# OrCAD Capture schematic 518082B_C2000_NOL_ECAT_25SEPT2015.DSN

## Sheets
1 SH01 - TITLE PAGE: title: C2000-ET1100 Adapter Board; rev: B; company: TEXAS INSTRUMENTS; note: 518082; note: Preliminary Information - Subject to change
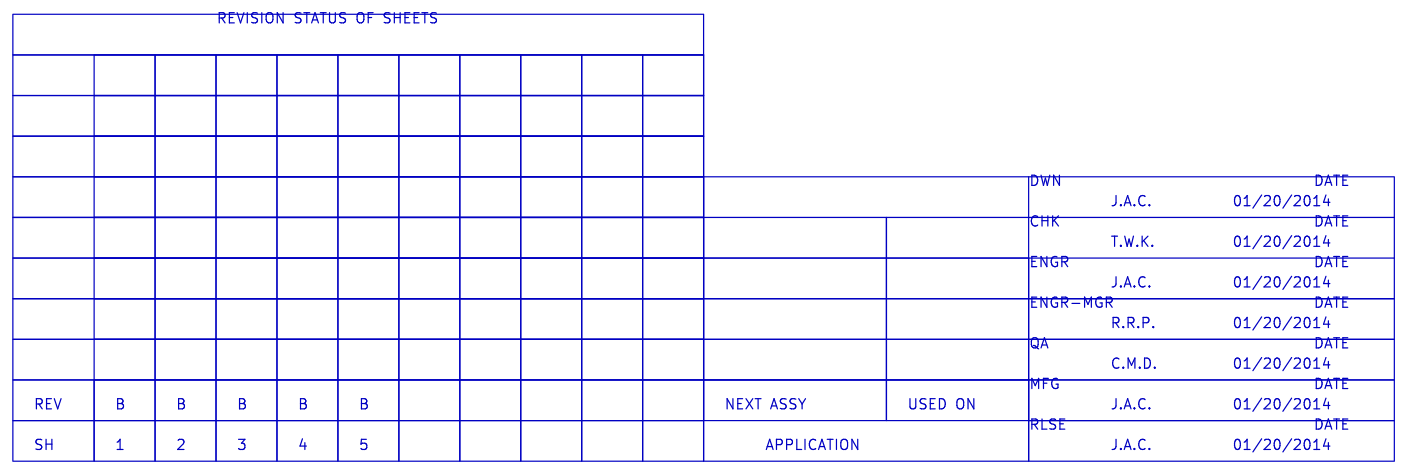
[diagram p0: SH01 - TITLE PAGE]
2 SH03 - ET1100: size C
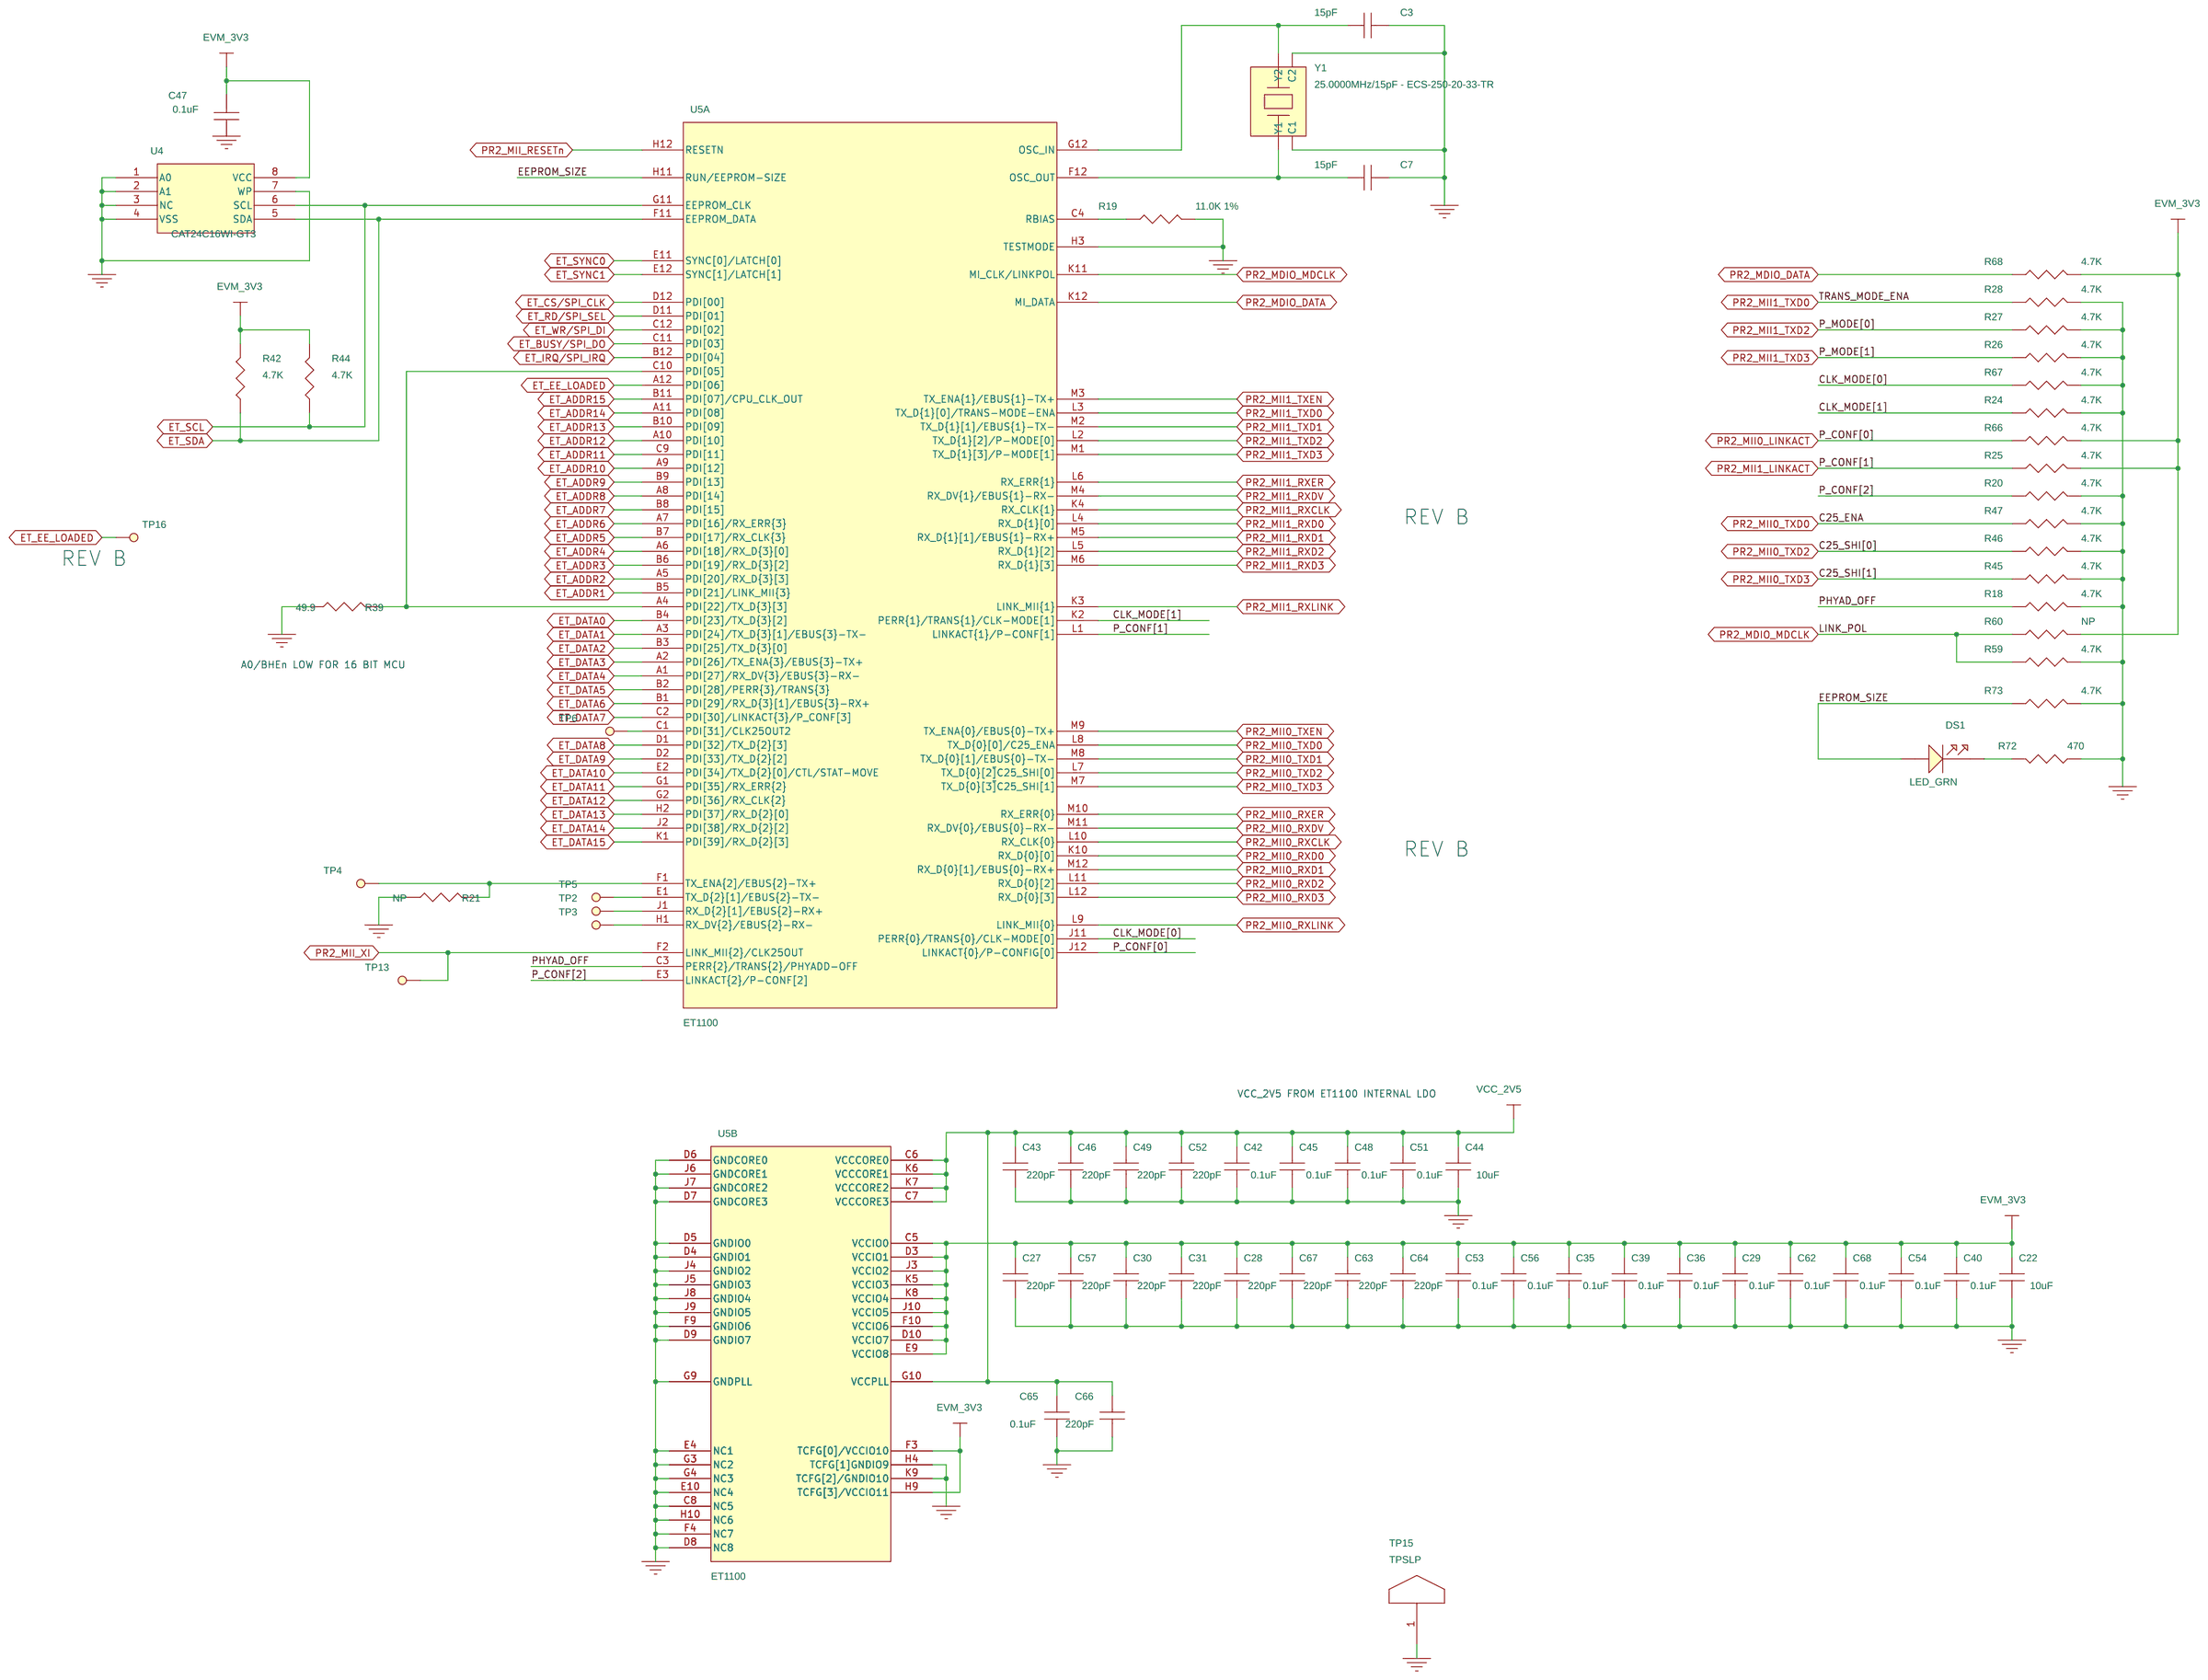
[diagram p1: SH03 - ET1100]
3 SH04 - ICCS2 Ethernet 0: size C
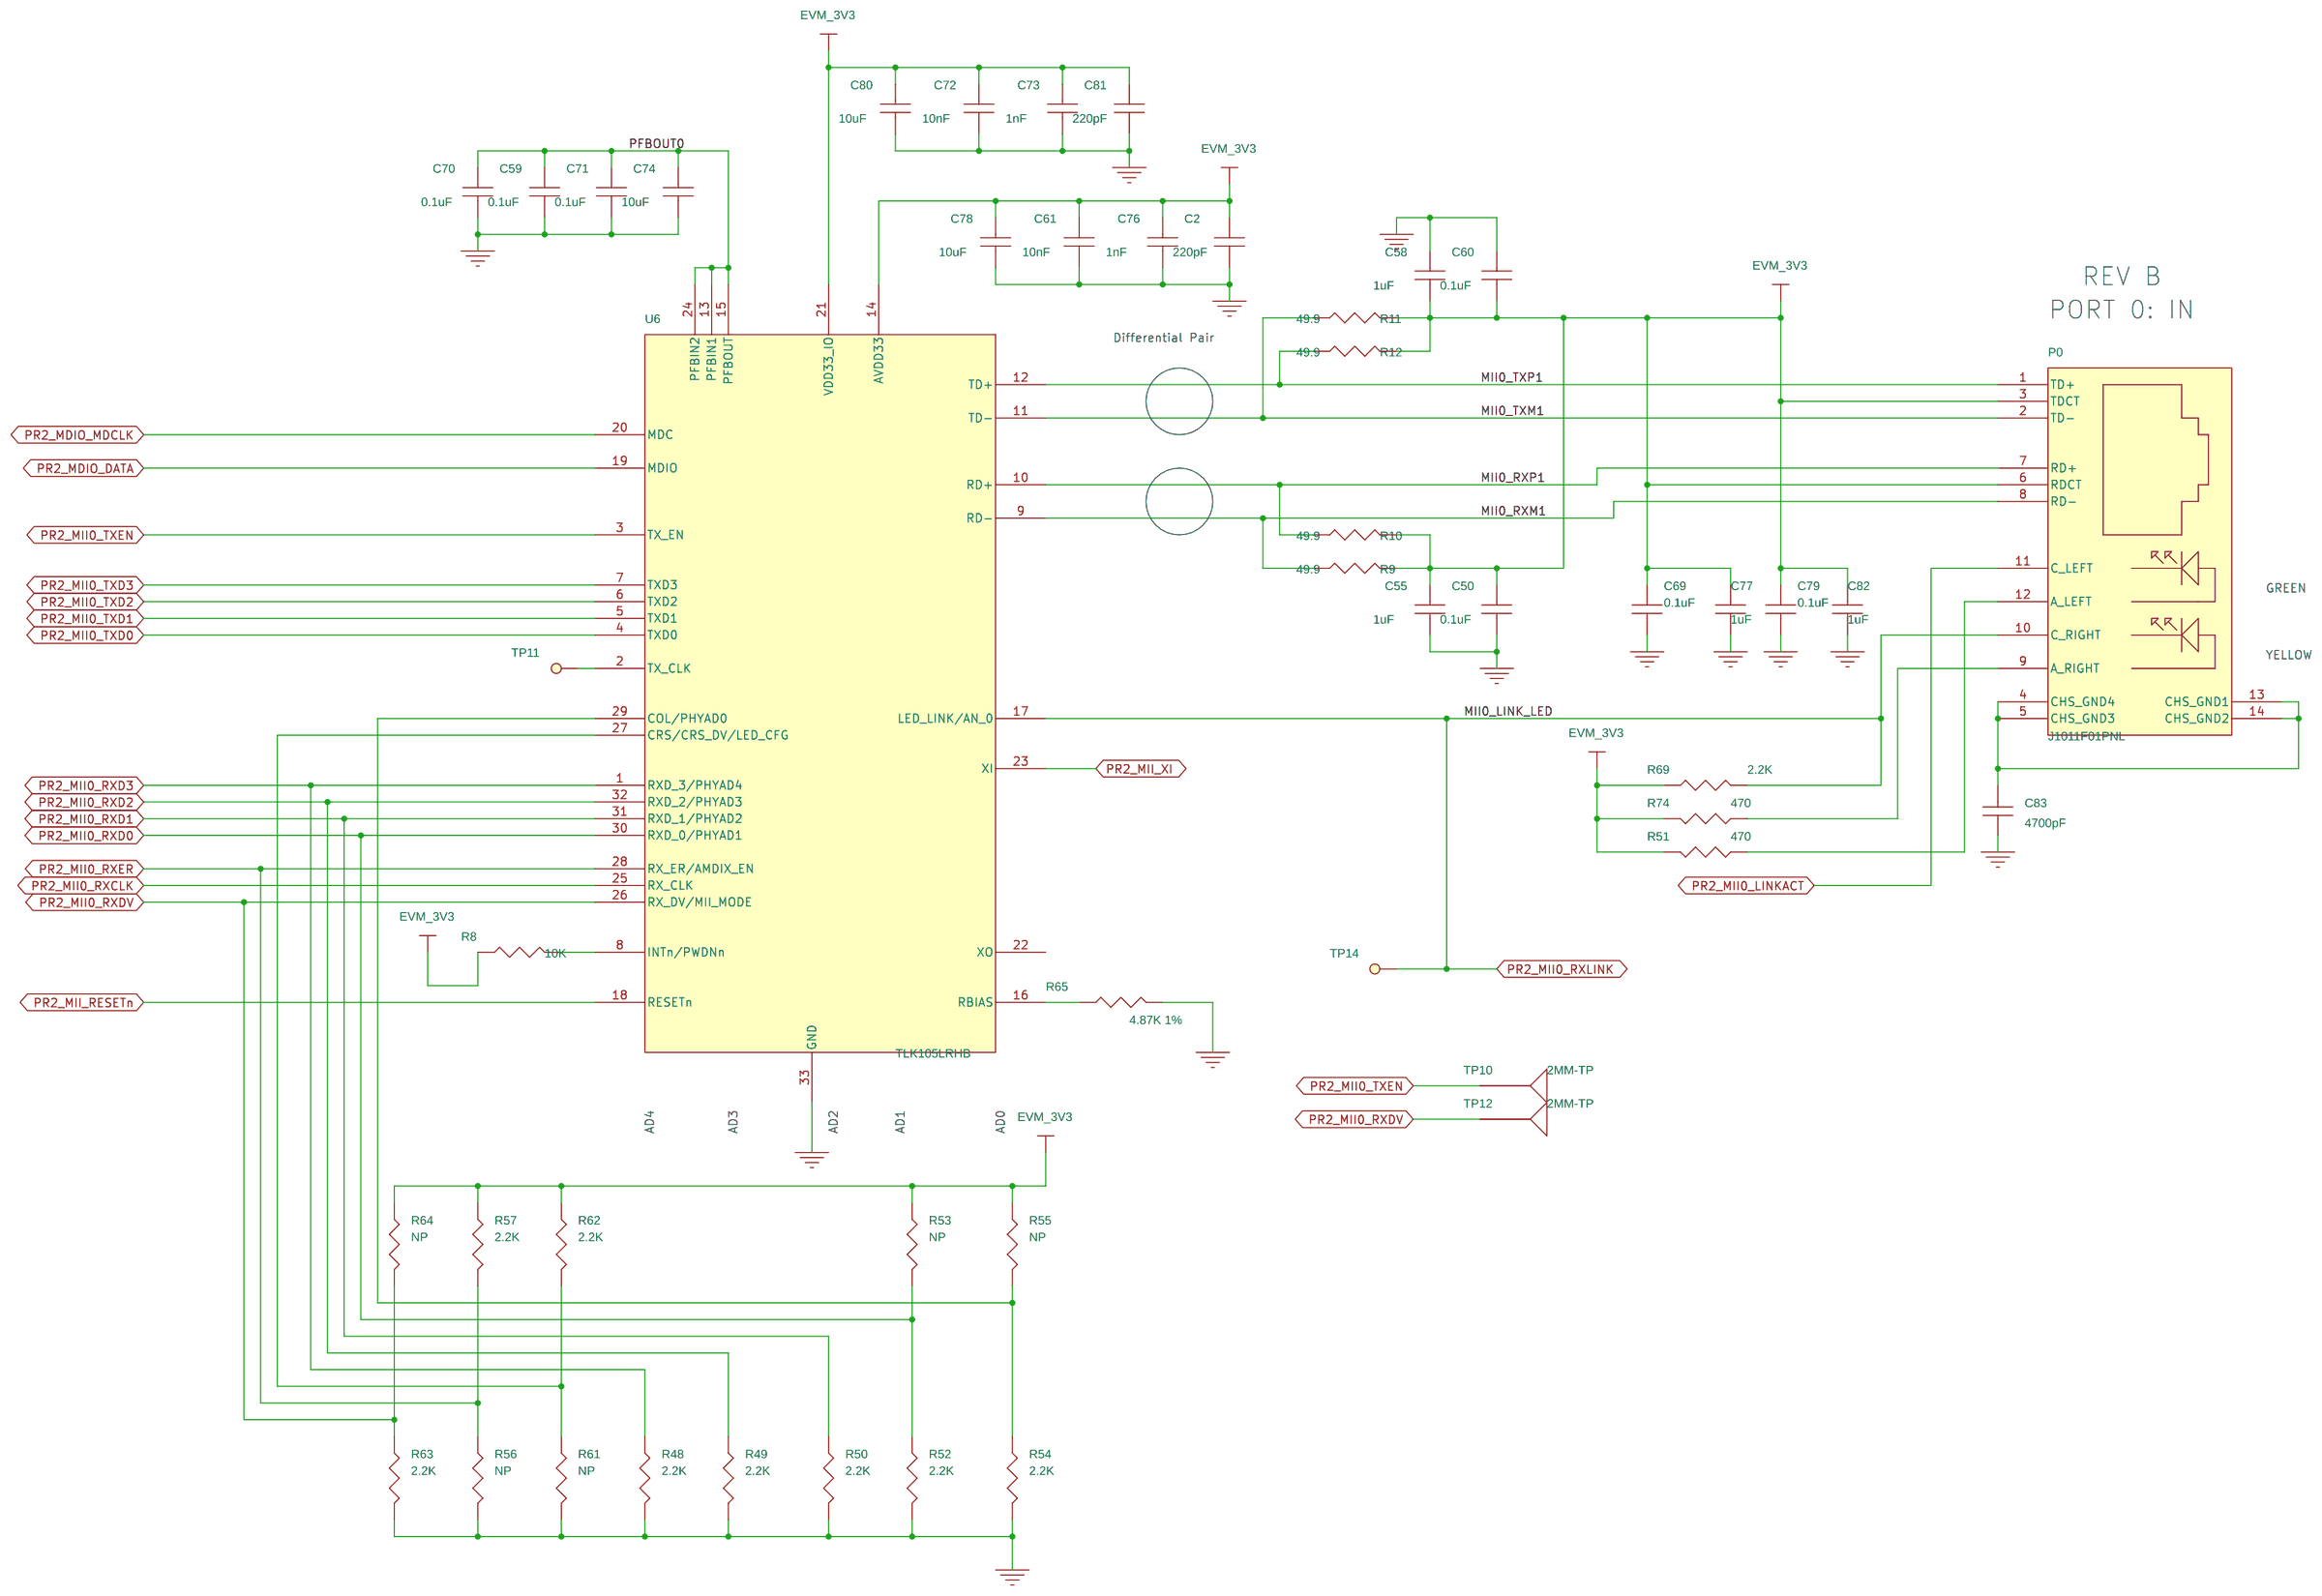
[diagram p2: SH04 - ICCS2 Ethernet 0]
4 SH05 - ICCS1 Ethernet 1: size C
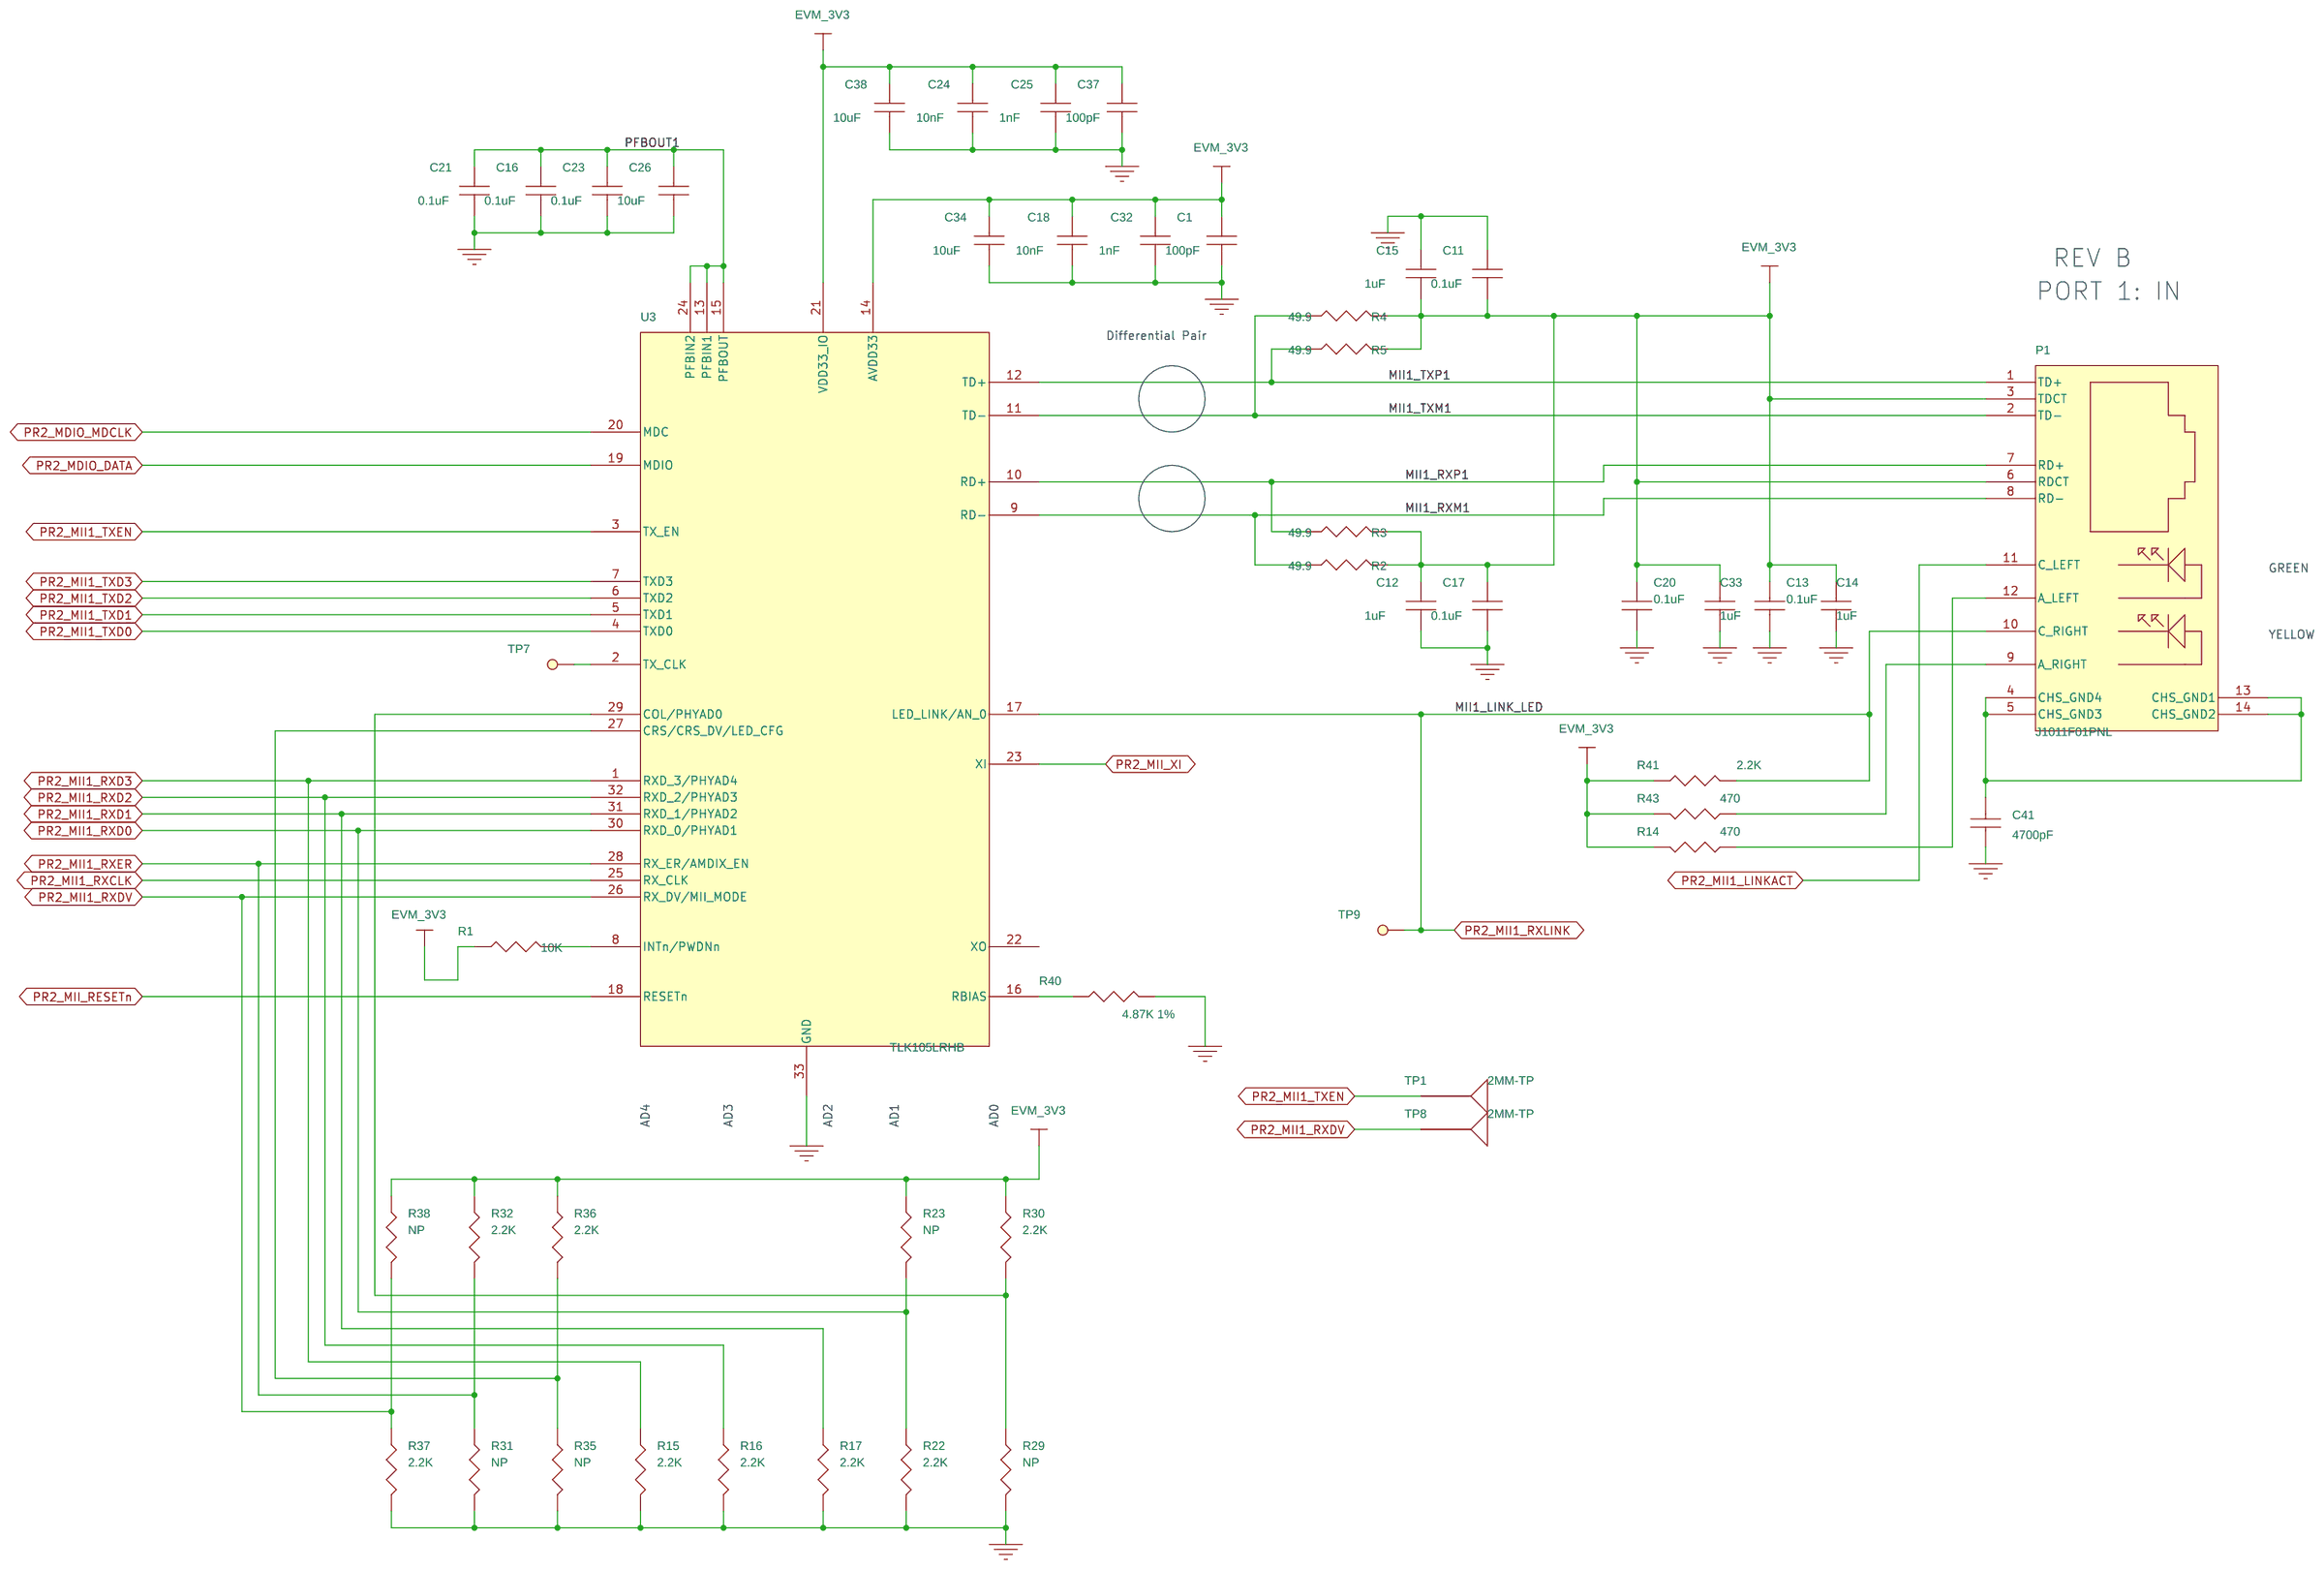
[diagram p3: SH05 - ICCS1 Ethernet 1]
5 SH02 - F28XX INTERFACE/POWER: size C
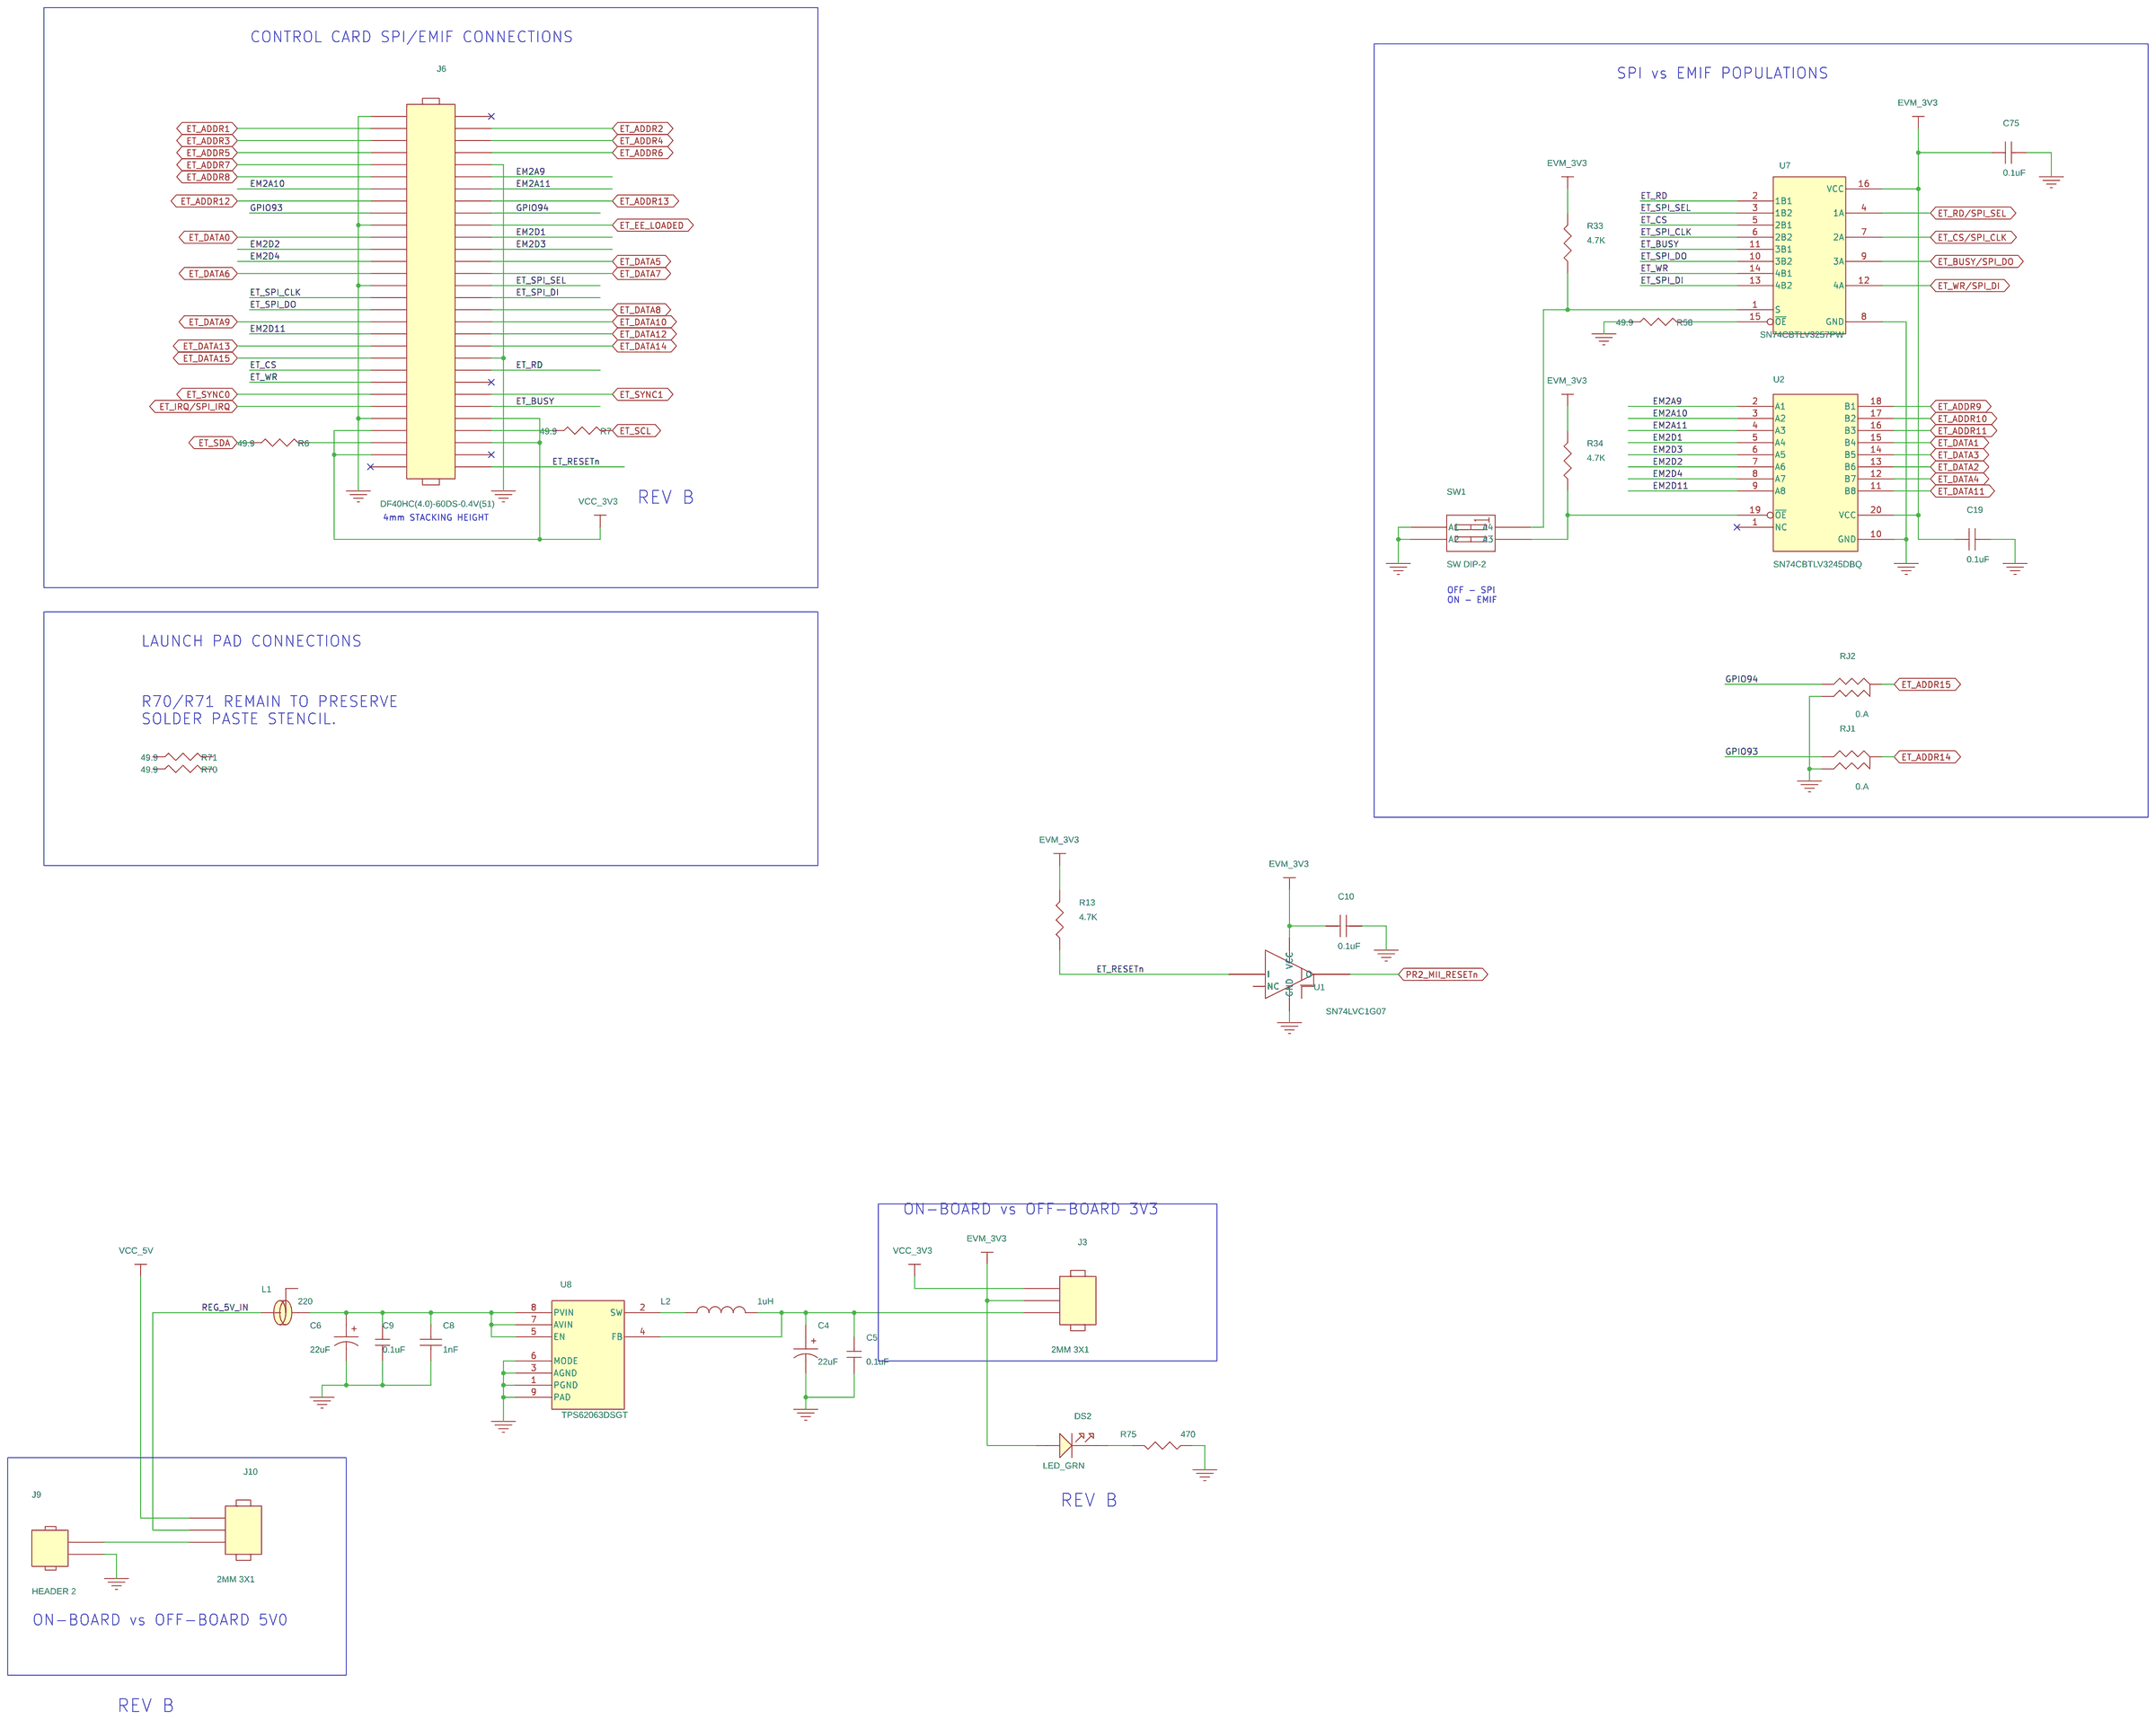
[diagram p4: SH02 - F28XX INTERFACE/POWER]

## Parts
sheet SH02 - F28XX INTERFACE/POWER
C4  22uF  [C1206-40X70]
C5  0.1uF  [c402-25]
C6  22uF  [C1206-40X70]
C8  1nF  [c402-25]
C9  0.1uF  [c402-25]
C10  0.1uF  [c402-25]
C19  0.1uF  [c402-25]
C75  0.1uF  [c402-25]
DS2  LED_GRN  [led1206-59x59]
J3  2MM 3X1  [hdr1x3-6040-2mm]
J6  DF40HC(4.0)-60DS-0.4V(51)  [df40c_60ds]
J9  HEADER 2  [conn2-eh]
J10  2MM 3X1  [hdr1x3-6040-2mm]
L1  220  [l603-35x45]
L2  1uH  [ind-LQH44p]
R6  49.9  [r402-25]
R7  49.9  [r402-25]
R13  4.7K  [r402-25]
R33  4.7K  [r402-25]
R34  4.7K  [r402-25]
R58  49.9  [r402-25]
R70  49.9  [r402-25]
R71  49.9  [r402-25]
R75  470  [r603-35X45]
RJ1  0.A  [JMP402-25]
RJ2  0.A  [JMP402-25]
SW1  SW DIP-2  [sw2-30x50-tda]
U1  SN74LVC1G07  [dck-5]
U2  SN74CBTLV3245DBQ  [dbq20-14X70]
U7  SN74CBTLV3257PW  [tssop16-14x70]
U8  TPS62063DSGT  [dsg8-11x20]
sheet SH03 - ET1100
C3  15pF  [c402-25]
C7  15pF  [c402-25]
C22  10uF  [c603-35x45]
C27  220pF  [c402-25]
C28  220pF  [c402-25]
C29  0.1uF  [c402-25]
C30  220pF  [c402-25]
C31  220pF  [c402-25]
C35  0.1uF  [c402-25]
C36  0.1uF  [c402-25]
C39  0.1uF  [c402-25]
C40  0.1uF  [c402-25]
C42  0.1uF  [c402-25]
C43  220pF  [c402-25]
C44  10uF  [c603-35x45]
C45  0.1uF  [c402-25]
C46  220pF  [c402-25]
C47  0.1uF  [c402-25]
C48  0.1uF  [c402-25]
C49  220pF  [c402-25]
C51  0.1uF  [c402-25]
C52  220pF  [c402-25]
C53  0.1uF  [c402-25]
C54  0.1uF  [c402-25]
C56  0.1uF  [c402-25]
C57  220pF  [c402-25]
C62  0.1uF  [c402-25]
C63  220pF  [c402-25]
C64  220pF  [c402-25]
C65  0.1uF  [c402-25]
C66  220pF  [c402-25]
C67  220pF  [c402-25]
C68  0.1uF  [c402-25]
DS1  LED_GRN  [led1206-59x59]
R18  4.7K  [r402-25]
R19  11.0K 1%  [r402-25]
R20  4.7K  [r402-25]
R21  NP  [r402-25]
R24  4.7K  [r402-25]
R25  4.7K  [r402-25]
R26  4.7K  [r402-25]
R27  4.7K  [r402-25]
R28  4.7K  [r402-25]
R39  49.9  [r402-25]
R42  4.7K  [r402-25]
R44  4.7K  [r402-25]
R45  4.7K  [r402-25]
R46  4.7K  [r402-25]
R47  4.7K  [r402-25]
R59  4.7K  [r402-25]
R60  NP  [r402-25]
R66  4.7K  [r402-25]
R67  4.7K  [r402-25]
R68  4.7K  [r402-25]
R72  470  [r603-35X45]
R73  4.7K  [r402-25]
TP2  RD30  [tp30]
TP3  RD30  [tp30]
TP4  RD30  [tp30]
TP5  RD30  [tp30]
TP6  RD30  [tp30]
TP13  RD30  [tp30]
TP15  TPSLP  [TP1-70X135]
TP16  RD30  [tp30]
U4  CAT24C16WI-GT3  [so8-25x75-295]
U5  ET1100  [bga128-8mm]  (sections A,B)
Y1  25.0000MHz/15pF - ECS-250-20-33-TR  [xtal4-47x51-ecx32]
sheet SH04 - ICCS2 Ethernet 0
C2  220pF  [c402-25]
C50  0.1uF  [c402-25]
C55  1uF  [c603-35x45]
C58  1uF  [c603-35x45]
C59  0.1uF  [c402-25]
C60  0.1uF  [c402-25]
C61  10nF  [c402-25]
C69  0.1uF  [c402-25]
C70  0.1uF  [c402-25]
C71  0.1uF  [c402-25]
C72  10nF  [c402-25]
C73  1nF  [c402-25]
C74  10uF  [c603-35x45]
C76  1nF  [c402-25]
C77  1uF  [c603-35x45]
C78  10uF  [c603-35x45]
C79  0.1uF  [c402-25]
C80  10uF  [c603-35x45]
C81  220pF  [c402-25]
C82  1uF  [c603-35x45]
C83  4700pF  [C1206-40X70]
P0  J1011F01PNL  [RJ45-PULSE_J1-SHLD]
R8  10K  [r402-25]
R9  49.9  [r402-25]
R10  49.9  [r402-25]
R11  49.9  [r402-25]
R12  49.9  [r402-25]
R48  2.2K  [r201-18p5x15]
R49  2.2K  [r201-18p5x15]
R50  2.2K  [r201-18p5x15]
R51  470  [r603-35X45]
R52  2.2K  [r201-18p5x15]
R53  NP  [r201-18p5x15]
R54  2.2K  [r201-18p5x15]
R55  NP  [r201-18p5x15]
R56  NP  [r201-18p5x15]
R57  2.2K  [r201-18p5x15]
R61  NP  [r201-18p5x15]
R62  2.2K  [r201-18p5x15]
R63  2.2K  [r201-18p5x15]
R64  NP  [r201-18p5x15]
R65  4.87K 1%  [r402-25]
R69  2.2K  [r201-18p5x15]
R74  470  [r603-35X45]
TP10  2MM-TP  [TP1-4020]
TP11  RD30  [tp30]
TP12  2MM-TP  [TP1-4020]
TP14  RD30  [tp30]
U6  TLK105LRHB  [QFN32_202SQ]
sheet SH05 - ICCS1 Ethernet 1
C1  100pF  [c402-25]
C11  0.1uF  [c402-25]
C12  1uF  [c603-35x45]
C13  0.1uF  [c402-25]
C14  1uF  [c603-35x45]
C15  1uF  [c603-35x45]
C16  0.1uF  [c402-25]
C17  0.1uF  [c402-25]
C18  10nF  [c402-25]
C20  0.1uF  [c402-25]
C21  0.1uF  [c402-25]
C23  0.1uF  [c402-25]
C24  10nF  [c402-25]
C25  1nF  [c402-25]
C26  10uF  [c603-35x45]
C32  1nF  [c402-25]
C33  1uF  [c603-35x45]
C34  10uF  [c603-35x45]
C37  100pF  [c402-25]
C38  10uF  [c603-35x45]
C41  4700pF  [C1206-40X70]
P1  J1011F01PNL  [RJ45-PULSE_J1-SHLD]
R1  10K  [r402-25]
R2  49.9  [r402-25]
R3  49.9  [r402-25]
R4  49.9  [r402-25]
R5  49.9  [r402-25]
R14  470  [r603-35X45]
R15  2.2K  [r201-18p5x15]
R16  2.2K  [r201-18p5x15]
R17  2.2K  [r201-18p5x15]
R22  2.2K  [r201-18p5x15]
R23  NP  [r201-18p5x15]
R29  NP  [r201-18p5x15]
R30  2.2K  [r201-18p5x15]
R31  NP  [r201-18p5x15]
R32  2.2K  [r201-18p5x15]
R35  NP  [r201-18p5x15]
R36  2.2K  [r201-18p5x15]
R37  2.2K  [r201-18p5x15]
R38  NP  [r201-18p5x15]
R40  4.87K 1%  [r402-25]
R41  2.2K  [r201-18p5x15]
R43  470  [r603-35X45]
TP1  2MM-TP  [TP1-4020]
TP7  RD30  [tp30]
TP8  2MM-TP  [TP1-4020]
TP9  RD30  [tp30]
U3  TLK105LRHB  [QFN32_202SQ]

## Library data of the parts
C4 = CAP_P_0: Part #: 101064-0221R
C5 C9 = CAP_NP_1: Part #: 104446-1100R
C6 = CAP_P_0: .1uf Capacitor, Ceramic, 16V, 10%, 0603; Cost100: 0.0694; Cost10K: 0.038; Mfr: Panasonic; MfrNum: ECJ-1VB1C104K; NCPartnumber: 1C0056; Part #: 101064-0221R; PartName: Cap 100nF Cermc 16V 10% 603; Vendor: Digi-Key; VendorNum: PCC1762CT-ND
C8 C25 C32 C73 C76 = CAP_NP: Part #: 101782-1102R
C10 C11 C16 C17 C19 C21 C23 C29 C35 C36 C39 C40 C42 C45 C48 C50 C51 C53 C54 C56 C59 C60 C62 C65 C68 C70 C71 C75 = CAP_NP: Part #: 104446-1100R
DS1 DS2 = LED_0: Part #: 100823-0001R
J3 J10 = HEADER_3: Part #: 100546-0003R
J6 = HEADER_30x2_SM: Part #: 104687-0060R
J9 = HEADER_2: Part #: 104699-0002R
L1 = FERRITE_CHIP_0: Part #: 101858-2201R
L2 = INDUCTOR_0: Part #: 104075-0100R
R2-R7 R9-R12 R39 R58 R70 R71 = R: Part #: 102145-4990R
R13 R18 R20 R24-R28 R33 R34 R42 R44-R47 R59 R66-R68 R73 = RESISTOR_0: Part #: 102145-4702R
R14 R43 R51 R72 R74 R75 = RESISTOR_0: Part #: 100687-4701R
RJ1 RJ2 = RJUMP3: Part #: 101370-0001R
SW1 = SW_DIP-2: Part #: 101184-0002R
U1 = SN74LVC1GU04_0: Part #: 101057-0007R; Spectrum Part#: 101027-0125
U2 = 74PCT245_0: Part #: 101659-0001R
U7 = SN74CBT3257PW: Part #: 101670-0001R
U8 = TPS62000: Part #: 104063-0001R
C3 C7 = CAP_NP_3: Part #: 101782-1154R
C22 C26 C34 C38 C44 C74 C78 C80 = CAP_NP: Part #: 102963-0101R
C2 C27 C28 C30 C31 C43 C46 C49 C52 C57 C63 C64 C66 C67 C81 = CAP_NP: Part #: 101782-1223R
C47 = CAP_.1_uF_10%_0603: Part #: 104446-1100R
R19 = RESISTOR_0: Part #: 102145-1103R
R21 = R: Part #: R0402-NOPOP
R60 = RESISTOR_0: Part #: R0402-NOPOP
TP2-TP7 TP9 TP11 TP13 TP14 TP16 = TestPoint1: Part #: SMT-TP030
TP15 = SMT-TP: Part #: 104178-0001R
U4 = 24WC256: Part #: 104686-0001R
U5 = ET1100: Part #: 104671-0001R-TI
Y1 = CRYSTAL_4-PIN_0: CRYSTAL, 25MHZ, 25PPM, 3.2X2.5,SMT; Part #: 103274-0025R
C12 C14 C15 C33 C55 C58 C77 C82 = CAP_NP: Part #: 101007-0100R
C18 C24 C61 C72 = CAP_NP: Part #: 101587-1101R
C13 C20 C69 C79 = CAP_NP_0: Part #: 104446-1100R; REV: A
C41 C83 = CAP_NP_0: Part #: 103604-1472R; REV: A
P0 P1 = J1011F01PNL: Part #: 104401-0001R
R1 R8 = R: Part #: 102145-1003R
R15-R17 R22 R30 R32 R36 R37 R41 R48-R50 R52 R54 R57 R62 R63 R69 = RESISTOR_0: Part #: 103158-2202R
R23 R29 R31 R35 R38 R53 R55 R56 R61 R64 = RESISTOR_0: Part #: R0201-NOPOP
R40 R65 = RESISTOR_0: Part #: 102145-4872R
TP1 TP8 TP10 TP12 = TEST_POINT_1: Part #: NO-POP
U3 U6 = TLK105: Part #: 104684-0001R
C1 C37 = CAP_NP: Part #: 101782-1103R

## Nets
GND: C1.2 C2.2 C3.2 C4.2 C5.2 C6.2 C7.2 C8.2 C9.2 C10.2 C11.1 C12.2 C13.2 C14.2 C15.1 C16.2 C17.2 C18.2 C19.2 C20.2 C21.2 C22.2 C23.2 C24.2 C25.2 C26.2 C27.2 C28.2 C29.2 C30.2 C31.2 C32.2 C33.2 C34.2 C35.2 C36.2 C37.2 C38.2 C39.2 C40.2 C41.1 C42.2 C43.2 C44.2 C45.2 C46.2 C47.1 C48.2 C49.2 C50.2 C51.2 C52.2 C53.2 C54.2 C55.2 C56.2 C57.2 C58.1 C59.2 C60.1 C61.2 C62.2 C63.2 C64.2 C65.2 C66.2 C67.2 C68.2 C69.2 C70.2 C71.2 C72.2 C73.2 C74.2 C75.2 C76.2 C77.2 C78.2 C79.2 C80.2 C81.2 C82.2 C83.1 J6.1 J6.10 J6.19 J6.29 J6.42 J6.51 J9.2 R15.2 R16.2 R17.2 R18.2 R19.2 R20.2 R21.1 R22.2 R24.2 R26.2 R27.2 R28.2 R29.2 R31.2 R35.2 R37.2 R39.1 R40.2 R45.2 R46.2 R47.2 R48.2 R49.2 R50.2 R52.2 R54.2 R56.2 R58.1 R59.2 R61.2 R63.2 R65.2 R67.2 R72.1 R73.2 R75.1 RJ1.3 RJ2.3 SW1.1(A1) SW1.2(A2) TP15.1 U1.3(GND) U2.10(GND) U3.33(GND) U4.1(A0) U4.2(A1) U4.3(NC) U4.4(VSS) U4.7(WP) U5.C8(NC5) U5.D4(GNDIO1) U5.D5(GNDIO0) U5.D6(GNDCORE0) U5.D7(GNDCORE3) U5.D8(NC8) U5.D9(GNDIO7) U5.E4(NC1) U5.E10(NC4) U5.F4(NC7) U5.F9(GNDIO6) U5.G3(NC2) U5.G4(NC3) U5.G9(GNDPLL) U5.H3(TESTMODE) U5.H4(TCFG[1]GNDIO9) U5.H10(NC6) U5.J4(GNDIO2) U5.J5(GNDIO3) U5.J6(GNDCORE1) U5.J7(GNDCORE2) U5.J8(GNDIO4) U5.J9(GNDIO5) U5.K9(TCFG[2]/GNDIO10) U6.33(GND) U7.8(GND) U8.1(PGND) U8.3(AGND) U8.6(MODE) U8.9(PAD) Y1.2(C1) Y1.4(C2)
VCC_2V5: C42.1 C43.1 C44.1 C45.1 C46.1 C48.1 C49.1 C51.1 C52.1 C65.1 C66.1 U5.C6(VCCCORE0) U5.C7(VCCCORE3) U5.G10(VCCPLL) U5.K6(VCCCORE1) U5.K7(VCCCORE2)
VCC_3V3: J3.1 J6.52 J6.53 J6.56 J6.57
VCC_5V: J10.1
CLK_MODE[0]: R67.1 U5.J11(PERR{0}/TRANS{0}/CLK-MODE[0])
CLK_MODE[1]: R24.1 U5.K2(PERR{1}/TRANS{1}/CLK-MODE[1])
EEPROM_SIZE: DS1.2(ANODE) R73.1 U5.H11(RUN/EEPROM-SIZE)
EM2A9: J6.12 U2.2(A1)
EM2A10: J6.13 U2.3(A2)
EM2A11: J6.14 U2.4(A3)
EM2D1: J6.22 U2.5(A4)
EM2D2: J6.23 U2.7(A6)
EM2D3: J6.24 U2.6(A5)
EM2D4: J6.25 U2.8(A7)
EM2D11: J6.37 U2.9(A8)
ET_ADDR1: J6.3 U5.B5(PDI[21]/LINK_MII{3})
ET_ADDR2: J6.4 U5.A5(PDI[20]/RX_D{3}[3])
ET_ADDR3: J6.5 U5.B6(PDI[19]/RX_D{3}[2])
ET_ADDR4: J6.6 U5.A6(PDI[18]/RX_D{3}[0])
ET_ADDR5: J6.7 U5.B7(PDI[17]/RX_CLK{3})
ET_ADDR6: J6.8 U5.A7(PDI[16]/RX_ERR{3})
ET_ADDR7: J6.9 U5.B8(PDI[15])
ET_ADDR8: J6.11 U5.A8(PDI[14])
ET_ADDR9: U2.18(B1) U5.B9(PDI[13])
ET_ADDR10: U2.17(B2) U5.A9(PDI[12])
ET_ADDR11: U2.16(B3) U5.C9(PDI[11])
ET_ADDR12: J6.15 U5.A10(PDI[10])
ET_ADDR13: J6.16 U5.B10(PDI[09])
ET_ADDR14: RJ1.2 U5.A11(PDI[08])
ET_ADDR15: RJ2.2 U5.B11(PDI[07]/CPU_CLK_OUT)
ET_BUSY: J6.50 U7.11(3B1)
ET_BUSY/SPI_DO: U5.C11(PDI[03]) U7.9(3A)
ET_CS: J6.43 U7.5(2B1)
ET_CS/SPI_CLK: U5.D12(PDI[00]) U7.7(2A)
ET_DATA0: J6.21 U5.B4(PDI[23]/TX_D{3}[2])
ET_DATA1: U2.15(B4) U5.A3(PDI[24]/TX_D{3}[1]/EBUS{3}-TX-)
ET_DATA2: U2.13(B6) U5.B3(PDI[25]/TX_D{3}[0])
ET_DATA3: U2.14(B5) U5.A2(PDI[26]/TX_ENA{3}/EBUS{3}-TX+)
ET_DATA4: U2.12(B7) U5.A1(PDI[27]/RX_DV{3}/EBUS{3}-RX-)
ET_DATA5: J6.26 U5.B2(PDI[28]/PERR{3}/TRANS{3})
ET_DATA6: J6.27 U5.B1(PDI[29]/RX_D{3}[1]/EBUS{3}-RX+)
ET_DATA7: J6.28 U5.C2(PDI[30]/LINKACT{3}/P_CONF[3])
ET_DATA8: J6.34 U5.D1(PDI[32]/TX_D{2}[3])
ET_DATA9: J6.35 U5.D2(PDI[33]/TX_D{2}[2])
ET_DATA10: J6.36 U5.E2(PDI[34]/TX_D{2}[0]/CTL/STAT-MOVE)
ET_DATA11: U2.11(B8) U5.G1(PDI[35]/RX_ERR{2})
ET_DATA12: J6.38 U5.G2(PDI[36]/RX_CLK{2})
ET_DATA13: J6.39 U5.H2(PDI[37]/RX_D{2}[0])
ET_DATA14: J6.40 U5.J2(PDI[38]/RX_D{2}[2])
ET_DATA15: J6.41 U5.K1(PDI[39]/RX_D{2}[3])
ET_EE_LOADED: J6.20 TP16.1 U5.A12(PDI[06])
ET_IRQ/SPI_IRQ: J6.49 U5.B12(PDI[04])
ET_RD: J6.44 U7.2(1B1)
ET_RD/SPI_SEL: U5.D11(PDI[01]) U7.4(1A)
ET_RESETn: J6.60 R13.1 U1.2(I)
ET_SCL: R7.2 R44.1 U4.6(SCL) U5.G11(EEPROM_CLK)
ET_SDA: R6.1 R42.1 U4.5(SDA) U5.F11(EEPROM_DATA)
ET_SPI_CLK: J6.31 U7.6(2B2)
ET_SPI_DI: J6.32 U7.13(4B2)
ET_SPI_DO: J6.33 U7.10(3B2)
ET_SPI_SEL: J6.30 U7.3(1B2)
ET_SYNC0: J6.47 U5.E11(SYNC[0]/LATCH[0])
ET_SYNC1: J6.48 U5.E12(SYNC[1]/LATCH[1])
ET_WR: J6.45 U7.14(4B1)
ET_WR/SPI_DI: U5.C12(PDI[02]) U7.12(4A)
EVM_3V3: C1.1 C2.1 C10.1 C11.2 C12.1 C13.1 C14.1 C15.2 C17.1 C18.1 C19.1 C20.1 C22.1 C24.1 C25.1 C27.1 C28.1 C29.1 C30.1 C31.1 C32.1 C33.1 C34.1 C35.1 C36.1 C37.1 C38.1 C39.1 C40.1 C47.2 C50.1 C53.1 C54.1 C55.1 C56.1 C57.1 C58.2 C60.2 C61.1 C62.1 C63.1 C64.1 C67.1 C68.1 C69.1 C72.1 C73.1 C75.1 C76.1 C77.1 C78.1 C79.1 C80.1 C81.1 C82.1 DS2.2(ANODE) J3.2 P0.3(TDCT) P0.6(RDCT) P1.3(TDCT) P1.6(RDCT) R1.1 R2.2 R3.2 R4.2 R5.2 R8.1 R9.2 R10.2 R11.2 R12.2 R13.2 R14.2 R23.1 R25.2 R30.1 R32.1 R33.2 R34.2 R36.1 R38.1 R41.1 R42.2 R43.2 R44.2 R51.2 R53.1 R55.1 R57.1 R60.2 R62.1 R64.1 R66.2 R68.2 R69.1 R74.2 U1.5(VCC) U2.20(VCC) U3.14(AVDD33) U3.21(VDD33_IO) U4.8(VCC) U5.C5(VCCIO0) U5.D3(VCCIO1) U5.D10(VCCIO7) U5.E9(VCCIO8) U5.F3(TCFG[0]/VCCIO10) U5.F10(VCCIO6) U5.H9(TCFG[3]/VCCIO11) U5.J3(VCCIO2) U5.J10(VCCIO5) U5.K5(VCCIO3) U5.K8(VCCIO4) U6.14(AVDD33) U6.21(VDD33_IO) U7.16(VCC)
GPIO93: J6.17 RJ1.1
GPIO94: J6.18 RJ2.1
MII0_RXM1: P0.8(RD-) R9.1 U6.9(RD-)
MII0_RXP1: P0.7(RD+) R10.1 U6.10(RD+)
MII0_TXM1: P0.2(TD-) R11.1 U6.11(TD-)
MII0_TXP1: P0.1(TD+) R12.1 U6.12(TD+)
MII1_RXM1: P1.8(RD-) R2.1 U3.9(RD-)
MII1_RXP1: P1.7(RD+) R3.1 U3.10(RD+)
MII1_TXM1: P1.2(TD-) R4.1 U3.11(TD-)
MII1_TXP1: P1.1(TD+) R5.1 U3.12(TD+)
P_CONF[2]: R20.1 U5.E3(LINKACT{2}/P-CONF[2])
PFBOUT0: C59.1 C70.1 C71.1 C74.1 U6.13(PFBIN1) U6.15(PFBOUT) U6.24(PFBIN2)
PFBOUT1: C16.1 C21.1 C23.1 C26.1 U3.13(PFBIN1) U3.15(PFBOUT) U3.24(PFBIN2)
PHYAD_OFF: R18.1 U5.C3(PERR{2}/TRANS{2}/PHYADD-OFF)
PR2_MDIO_DATA: R68.1 U3.19(MDIO) U5.K12(MI_DATA) U6.19(MDIO)
PR2_MDIO_MDCLK: R59.1 R60.1 U3.20(MDC) U5.K11(MI_CLK/LINKPOL) U6.20(MDC)
PR2_MII0_LINKACT: P0.11(C_LEFT) R66.1 U5.J12(LINKACT{0}/P-CONFIG[0])
PR2_MII0_RXCLK: U5.L10(RX_CLK{0}) U6.25(RX_CLK)
PR2_MII0_RXD0: R52.1 R53.2 U5.K10(RX_D{0}[0]) U6.30(RXD_0/PHYAD1)
PR2_MII0_RXD1: R50.1 U5.M12(RX_D{0}[1]/EBUS{0}-RX+) U6.31(RXD_1/PHYAD2)
PR2_MII0_RXD2: R49.1 U5.L11(RX_D{0}[2]) U6.32(RXD_2/PHYAD3)
PR2_MII0_RXD3: R48.1 U5.L12(RX_D{0}[3]) U6.1(RXD_3/PHYAD4)
PR2_MII0_RXDV: R63.1 R64.2 TP12.1 U5.M11(RX_DV{0}/EBUS{0}-RX-) U6.26(RX_DV/MII_MODE)
PR2_MII0_RXER: R56.1 R57.2 U5.M10(RX_ERR{0}) U6.28(RX_ER/AMDIX_EN)
PR2_MII0_RXLINK: P0.10(C_RIGHT) R69.2 TP14.1 U5.L9(LINK_MII{0}) U6.17(LED_LINK/AN_0)
PR2_MII0_TXD0: R47.1 U5.L8(TX_D{0}[0]/C25_ENA) U6.4(TXD0)
PR2_MII0_TXD1: U5.M8(TX_D{0}[1]/EBUS{0}-TX-) U6.5(TXD1)
PR2_MII0_TXD2: R46.1 U5.L7(TX_D{0}[2~{]}C25_SHI[0]) U6.6(TXD2)
PR2_MII0_TXD3: R45.1 U5.M7(TX_D{0}[3~{]}C25_SHI[1]) U6.7(TXD3)
PR2_MII0_TXEN: TP10.1 U5.M9(TX_ENA{0}/EBUS{0}-TX+) U6.3(TX_EN)
PR2_MII1_LINKACT: P1.11(C_LEFT) R25.1 U5.L1(LINKACT{1}/P-CONF[1])
PR2_MII1_RXCLK: U3.25(RX_CLK) U5.K4(RX_CLK{1})
PR2_MII1_RXD0: R22.1 R23.2 U3.30(RXD_0/PHYAD1) U5.L4(RX_D{1}[0])
PR2_MII1_RXD1: R17.1 U3.31(RXD_1/PHYAD2) U5.M5(RX_D{1}[1]/EBUS{1}-RX+)
PR2_MII1_RXD2: R16.1 U3.32(RXD_2/PHYAD3) U5.L5(RX_D{1}[2])
PR2_MII1_RXD3: R15.1 U3.1(RXD_3/PHYAD4) U5.M6(RX_D{1}[3])
PR2_MII1_RXDV: R37.1 R38.2 TP8.1 U3.26(RX_DV/MII_MODE) U5.M4(RX_DV{1}/EBUS{1}-RX-)
PR2_MII1_RXER: R31.1 R32.2 U3.28(RX_ER/AMDIX_EN) U5.L6(RX_ERR{1})
PR2_MII1_RXLINK: P1.10(C_RIGHT) R41.2 TP9.1 U3.17(LED_LINK/AN_0) U5.K3(LINK_MII{1})
PR2_MII1_TXD0: R28.1 U3.4(TXD0) U5.L3(TX_D{1}[0]/TRANS-MODE-ENA)
PR2_MII1_TXD1: U3.5(TXD1) U5.M2(TX_D{1}[1]/EBUS{1}-TX-)
PR2_MII1_TXD2: R27.1 U3.6(TXD2) U5.L2(TX_D{1}[2]/P-MODE[0])
PR2_MII1_TXD3: R26.1 U3.7(TXD3) U5.M1(TX_D{1}[3]/P-MODE[1])
PR2_MII1_TXEN: TP1.1 U3.3(TX_EN) U5.M3(TX_ENA{1}/EBUS{1}-TX+)
PR2_MII_RESETn: U1.4(O) U3.18(RESETn) U5.H12(RESETN) U6.18(RESETn)
PR2_MII_XI: TP13.1 U3.23(XI) U5.F2(LINK_MII{2}/CLK25OUT) U6.23(XI)
REG_5V_IN: J10.2 L1.1
N21750864: R54.1 R55.2 U6.29(COL/PHYAD0)
N21750872: R61.1 R62.2 U6.27(CRS/CRS_DV/LED_CFG)
N21750878: R65.1 U6.16(RBIAS)
N21751363: P0.9(A_RIGHT) R74.1
N21751679: C83.2 P0.4(CHS_GND4) P0.5(CHS_GND3) P0.13(CHS_GND1) P0.14(CHS_GND2)
N21752228: R8.2 U6.8(INTn/PWDNn)
N21760792: R29.1 R30.2 U3.29(COL/PHYAD0)
N21760889: R35.1 R36.2 U3.27(CRS/CRS_DV/LED_CFG)
N21760945: P1.9(A_RIGHT) R43.1
N21760963: C41.2 P1.4(CHS_GND4) P1.5(CHS_GND3) P1.13(CHS_GND1) P1.14(CHS_GND2)
N21761103: R40.1 U3.16(RBIAS)
N21761294: R1.2 U3.8(INTn/PWDNn)
N21764803: C7.1 U5.F12(OSC_OUT) Y1.1(Y1)
N21764807: C3.1 U5.G12(OSC_IN) Y1.3(Y2)
N21767563: R19.1 U5.C4(RBIAS)
N21781367: TP7.1 U3.2(TX_CLK)
N21781382: TP11.1 U6.2(TX_CLK)
N21785424: DS1.1(cathode) R72.2
N21788279: P1.12(A_LEFT) R14.1
N21789027: P0.12(A_LEFT) R51.1
N21791162: R21.2 TP4.1 U5.F1(TX_ENA{2]/EBUS{2}-TX+)
N21791165: TP5.1 U5.E1(TX_D{2}[1]/EBUS{2}-TX-)
N21791168: TP2.1 U5.J1(RX_D{2}[1]/EBUS{2}-RX+)
N21791171: TP3.1 U5.H1(RX_DV{2}/EBUS{2}-RX-)
N21791186: TP6.1 U5.C1(PDI[31]/CLK25OUT2)
N21791230: R39.2 U5.A4(PDI[22]/TX_D{3}[3]) U5.C10(PDI[05])
N21823994: C4.1 C5.1 J3.3 L2.2 U8.4(FB)
N21823999: L2.1 U8.2(SW)
N21824161: C6.1 C8.1 C9.1 L1.2 U8.5(EN) U8.7(AVIN) U8.8(PVIN)
N21833989: J6.54 R7.1
N21833992: J6.55 R6.2
N21843407: R33.1 SW1.4(A4) U7.1(S)
N21843411: R34.1 SW1.3(A3) U2.19(~{OE})
N21843710: R58.2 U7.15(~{OE})
N21870681: J9.1 J10.3
N21871502: DS2.1(cathode) R75.2

Not connected (* = marked no-connect by the designer): J6 2* 46* 58* 59*; R70 1 2; R71 1 2; U1 1(NC); U2 1(NC)*; U3 22(XO); U6 22(XO)

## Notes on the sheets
sheet 1
- REVISION STATUS OF SHEETS
- DWN
- DATE
- J.A.C.
- 01/20/2014
- CHK
- DATE
- T.W.K.
- 01/20/2014
- ENGR
- J.A.C.
- 01/20/2014
- DATE
- ENGR-MGR
- DATE
- R.R.P.
- 01/20/2014
- QA
- DATE
- C.M.D.
- 01/20/2014
- REV
- B
- B
- B
- B
- B
- NEXT ASSY
- USED ON
- MFG
- J.A.C.
- 01/20/2014
- DATE
- RLSE
- DATE
- SH
- 1
- 2
- 3
- 4
- 5
- APPLICATION
- J.A.C.
- 01/20/2014
sheet 2
- REV B
- REV B
- A0/BHEn LOW FOR 16 BIT MCU
- REV B
- VCC_2V5 FROM ET1100 INTERNAL LDO
sheet 3
- REV B
- PORT 0: IN
- Differential Pair
- GREEN
- YELLOW
- AD4
- AD3
- AD2
- AD1
- AD0
sheet 4
- REV B
- PORT 1: IN
- Differential Pair
- GREEN
- YELLOW
- AD4
- AD3
- AD2
- AD1
- AD0
sheet 5
- CONTROL CARD SPI/EMIF CONNECTIONS
- SPI vs EMIF POPULATIONS
- REV B
- 4mm STACKING HEIGHT
- OFF - SPI
  ON - EMIF
- LAUNCH PAD CONNECTIONS
- R70/R71 REMAIN TO PRESERVE
  SOLDER PASTE STENCIL.
- ON-BOARD vs OFF-BOARD 3V3
- REV B
- ON-BOARD vs OFF-BOARD 5V0
- REV B
